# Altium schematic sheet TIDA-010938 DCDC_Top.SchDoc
size 431 x 279 mm; Date: Not shown in title block; ApprovedBy: Not shown in title block; CheckedBy: Not shown in title block; Author: Not shown in title block; CompanyName: Not shown in title block; Engineer: Not shown in title block; Organization: Not shown in title block; Address1: Not shown in title block; Address2: Not shown in title block; Address3: Not shown in title block; Address4: Not shown in title block; DocumentNumber: 1; Revision: Use project parameter SCH_Rev; SheetNumber: 2; SheetTotal: 9; PageSetup: Record=PageOptions¦CenterHorizontal=True¦CenterVertical=True¦PrintScale=1.00¦XCorrection=1.00¦YCorrection=1.00¦PrintKind=0¦BorderSize=5000000¦LeftOffset=0¦BottomOffset=0¦Orientation=2¦PaperLength=1000¦PaperWidth=1000¦Scale=100¦PaperSource=15¦PrintQuality=600¦MediaType=1¦DitherType=10¦PaperKind=Letter¦PrintScaleMode=1
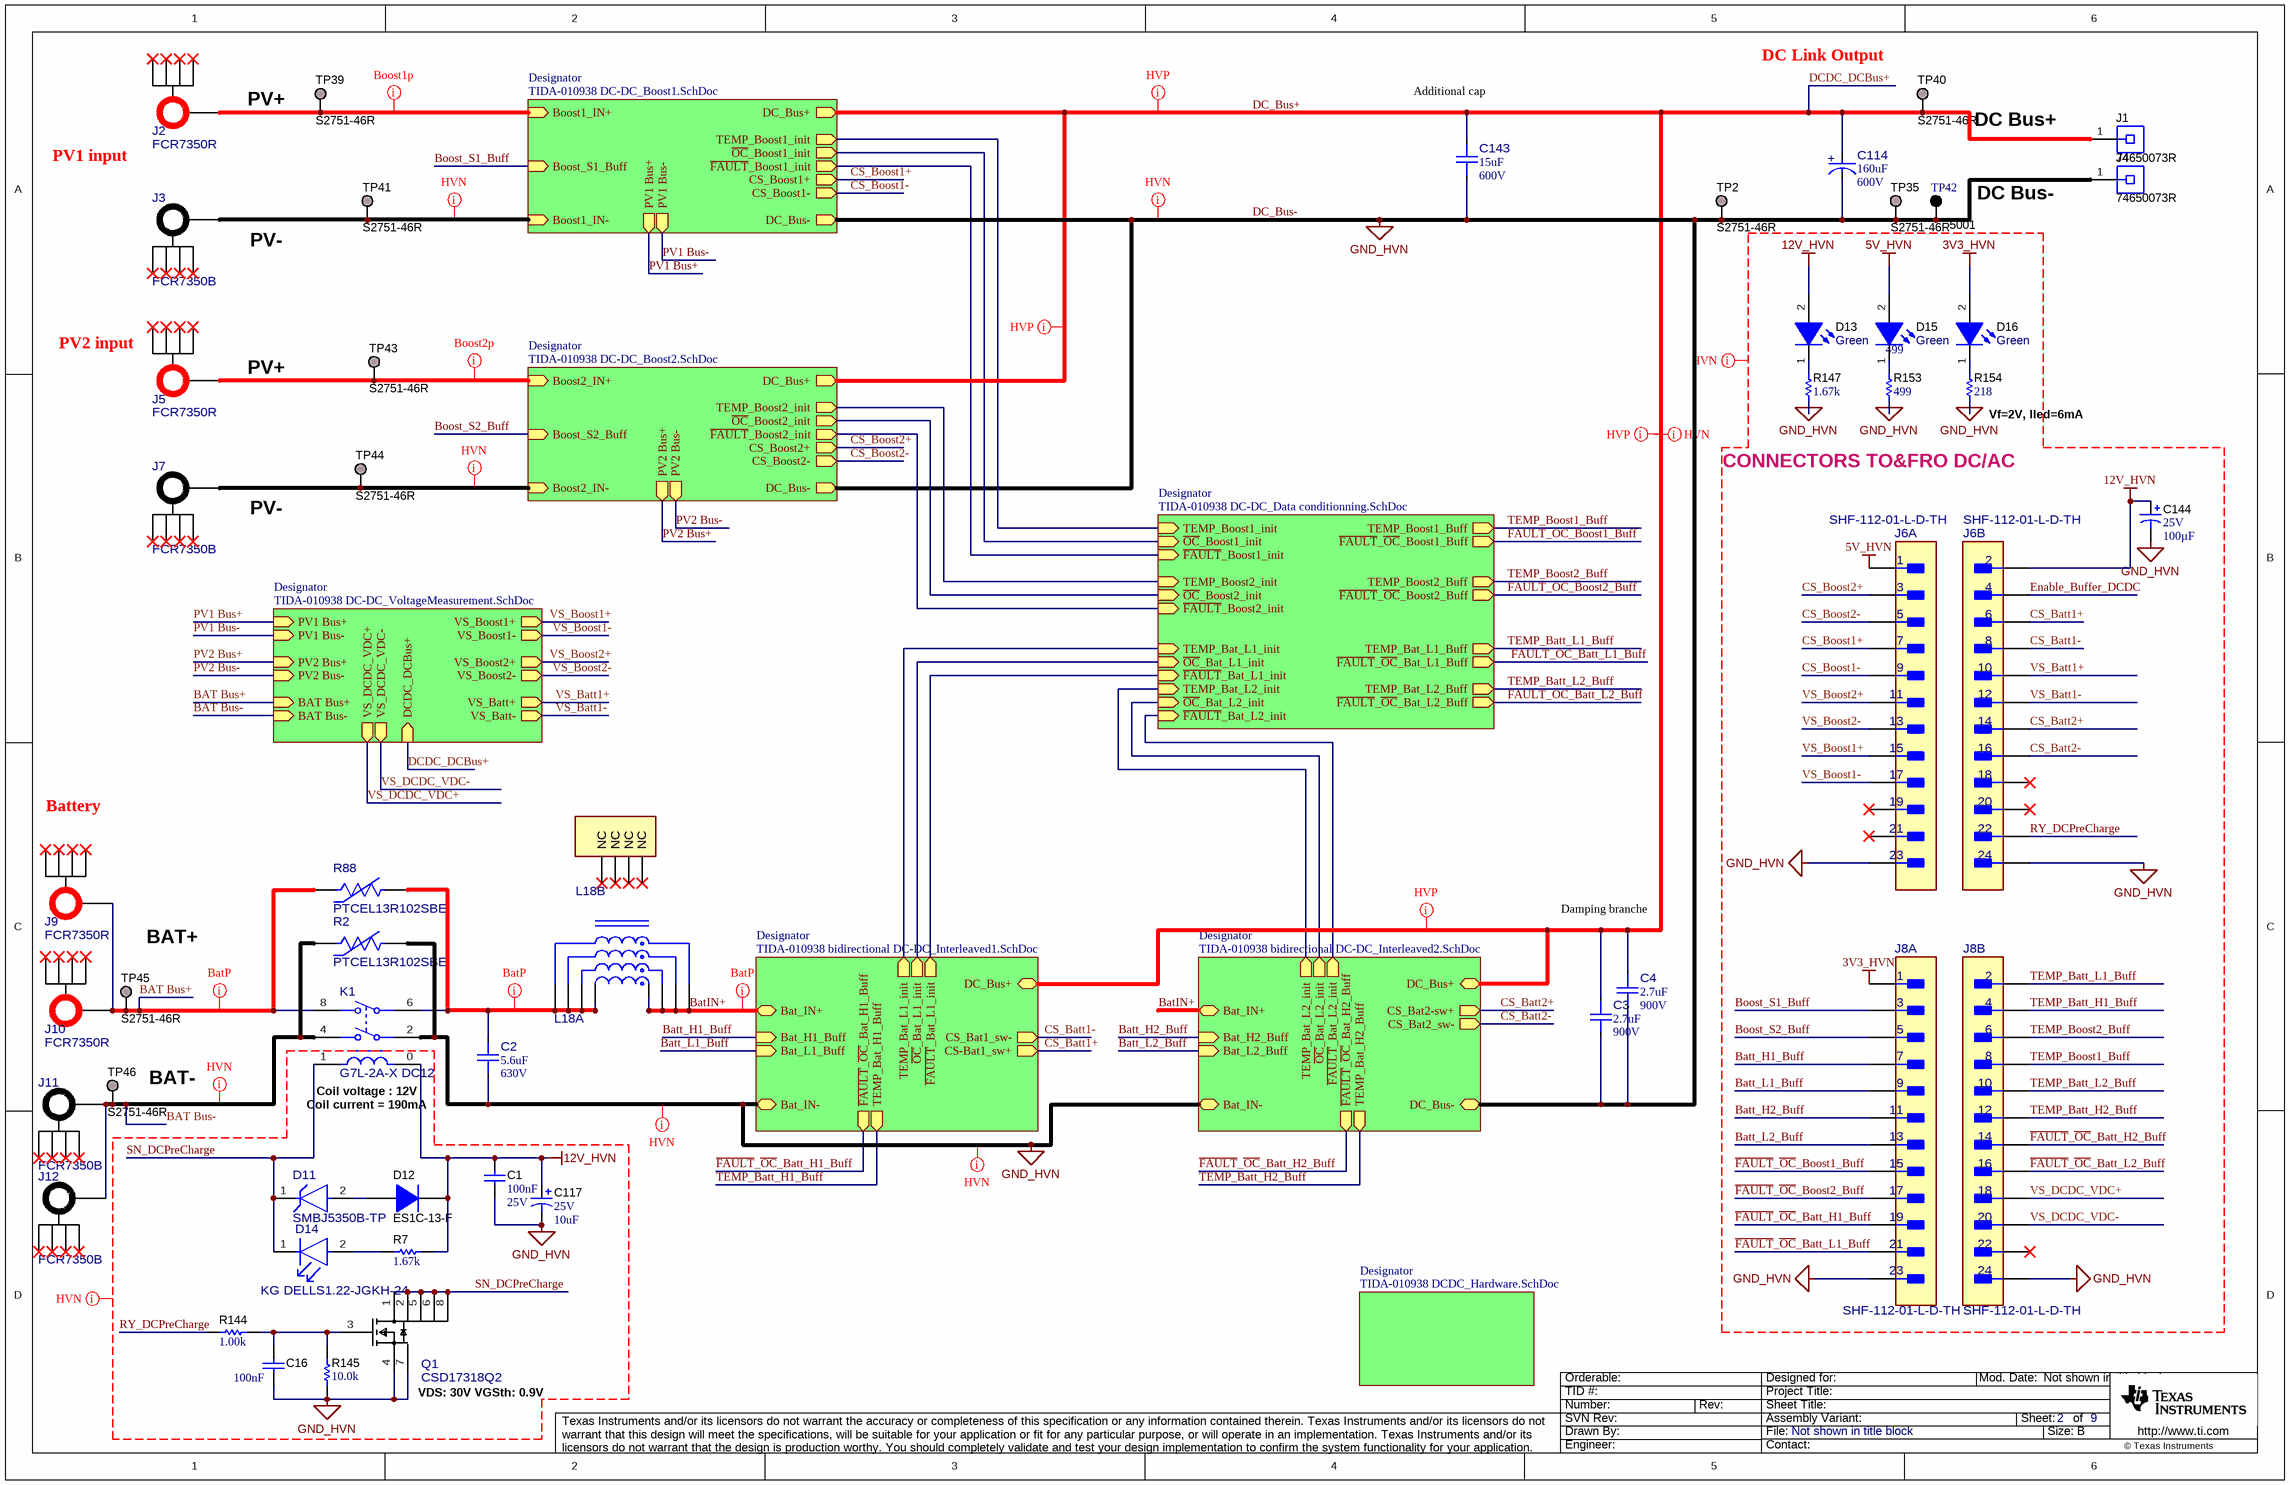
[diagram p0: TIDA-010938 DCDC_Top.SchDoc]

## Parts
C1  Cap_F: 100nF  VDC_V: 25V  [0603]  (hidden comment: 06033C104JAT2A)
C2  ValueDisplayed: 5.6uF  VDC_V: 630V  [FP-R533R456050P0M_RADIAL-MFG]  (hidden comment: R533R456050P0M)
C3  ValueDisplayed: 2.7uF  VDC_V: 900V  [FP-C4AKOBU4270A3YJ_RADIAL-MFG]  (hidden comment: C4AKOBU4270A3YJ)
C4  ValueDisplayed: 2.7uF  VDC_V: 900V  [FP-C4AKOBU4270A3YJ_RADIAL-MFG]  (hidden comment: C4AKOBU4270A3YJ)
C16  Cap_F: 100nF  [0603]  (hidden comment: GRM188R72A104KA35J)
C114  ValueDisplayed: 160uF  VDC_V: 600V  [FP-ALH82D161DD600_RADIAL-MFG]  (hidden comment: ALH82D161DD600)
C117  VDC_V: 25V  ValueDisplayed: 10uF  [SM_RADIAL_8MM]  (hidden comment: 25SVP10M)
C143  ValueDisplayed: 15uF  VDC_V: 600V  [FP-C4AQHBU5150P12J_RADIAL-MFG]  (hidden comment: C4AQHBU5150P12J)
C144  VDC_V: 25V  ValueDisplayed: 100µF  [UWT_630x770]  (hidden comment: UWT1E101MCL1GS)
D11  SMBJ5350B-TP  [FP-SMBJ5350B-TP_SMB-MFG]
D12  ES1C-13-F  [SMA]
D13  value Green  [WL-SMCW_GREEN]  (hidden comment: 150060VS75000)
D14  KG DELLS1.22-JGKH-24  [FP-KG DELLS1.22-JGKH-24_0603-MFG]
D15  value Green  [WL-SMCW_GREEN]  (hidden comment: 150060VS75000)
D16  value Green  [WL-SMCW_GREEN]  (hidden comment: 150060VS75000)
J1  74650073R  [Wurth_WP-THRBU]
J2  FCR7350R  [FP-FCR7350R_CONN_BANANA_JACK-MFG]
J3  FCR7350B  [FP-FCR7350B_CONN_BANANA_JACK-MFG]
J4  74650073R  [Wurth_WP-THRBU]
J5  FCR7350R  [FP-FCR7350R_CONN_BANANA_JACK-MFG]
J6  SHF-112-01-L-D-TH  [FP-SHF-112-01-L-D-TH_HDR24-MFG]  (parts A,B of 2)
J7  FCR7350B  [FP-FCR7350B_CONN_BANANA_JACK-MFG]
J8  SHF-112-01-L-D-TH  [FP-SHF-112-01-L-D-TH_HDR24-MFG]  (parts A,B of 2)
J9  FCR7350R  [FP-FCR7350R_CONN_BANANA_JACK-MFG]
J10  FCR7350R  [FP-FCR7350R_CONN_BANANA_JACK-MFG]
J11  FCR7350B  [FP-FCR7350B_CONN_BANANA_JACK-MFG]
J12  FCR7350B  [FP-FCR7350B_CONN_BANANA_JACK-MFG]
K1  G7L-2A-X DC12  [FP-G7L-2A-X DC12_PTH_RELAY_52MM5_35MM5-MFG]
L18  145454  [FP-145454_PTH12-MFG]  (value not drawn)  (parts A,B of 2)
Q1  CSD17318Q2  [FP-CSD17318Q2_WSON6-MFG]
R2  PTCEL13R102SBE  [FP-PTCEL13R102SBE_RADIAL-MFG]
R7  ValueDisplayed: 1.67k  [0603]  (hidden comment: RT0603DRE071K67L)
R88  PTCEL13R102SBE  [FP-PTCEL13R102SBE_RADIAL-MFG]
R144  ValueDisplayed: 1.00k  [0603]  (hidden comment: RNCF0603TKY1K00)
R145  ValueDisplayed: 10.0k  [0603]  (hidden comment: RG1608P-103-B-T5)
R147  ValueDisplayed: 1.67k  [0603]  (hidden comment: RT0603DRE071K67L)
R153  value 499  [0603]  (hidden comment: CRCW0603499RFKEAC)
R154  ValueDisplayed: 218  [0603]  (hidden comment: RT0603DRE07218RL)
TP2  S2751-46R  [Harwin_S2751-46R]  (no BOM)
TP35  S2751-46R  [Harwin_S2751-46R]  (no BOM)
TP39  S2751-46R  [Harwin_S2751-46R]  (no BOM)
TP40  S2751-46R  [Harwin_S2751-46R]  (no BOM)
TP41  S2751-46R  [Harwin_S2751-46R]  (no BOM)
TP42  5001  [Keystone5001]
TP43  S2751-46R  [Harwin_S2751-46R]  (no BOM)
TP44  S2751-46R  [Harwin_S2751-46R]  (no BOM)
TP45  S2751-46R  [Harwin_S2751-46R]  (no BOM)
TP46  S2751-46R  [Harwin_S2751-46R]  (no BOM)

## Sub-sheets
Designator = TIDA-010938 DC-DC_Boost1.SchDoc: Boost_S1_Buff (in), TEMP_Boost1_init (out), ~{FAULT}_Boost1_init (out), ~{OC}_Boost1_init (out), DC_Bus+ (out), DC_Bus- (out), Boost1_IN+ (in), Boost1_IN- (in), CS_Boost1+ (out), CS_Boost1- (out), PV1 Bus+ (out), PV1 Bus- (out)
Designator = TIDA-010938 DC-DC_Boost2.SchDoc: DC_Bus+ (out), DC_Bus- (out), Boost_S2_Buff (in), TEMP_Boost2_init (out), ~{FAULT}_Boost2_init (out), ~{OC}_Boost2_init (out), Boost2_IN+ (in), Boost2_IN- (in), CS_Boost2+ (out), CS_Boost2- (out), PV2 Bus+ (out), PV2 Bus- (out)
Designator = TIDA-010938 bidirectional DC-DC_Interleaved1.SchDoc: DC_Bus+ (bidir), Bat_IN+ (bidir), Bat_IN- (bidir), Bat_L1_Buff (in), Bat_H1_Buff (in), ~{FAULT}_Bat_L1_init (out), ~{FAULT}_~{OC}_Bat_H1_Buff (out), ~{OC}_Bat_L1_init (out), TEMP_Bat_H1_Buff (out), TEMP_Bat_L1_init (out), CS_Bat1_sw- (out), CS-Bat1_sw+ (out)
Designator = TIDA-010938 DC-DC_VoltageMeasurement.SchDoc: PV1 Bus+ (in), PV2 Bus+ (in), VS_Boost2+ (out), BAT Bus+ (in), BAT Bus- (in), VS_Batt+ (out), VS_Boost1+ (out), VS_Batt- (out), VS_Boost2- (out), VS_Boost1- (out), PV2 Bus- (in), PV1 Bus- (in), DCDC_DCBus+ (in), VS_DCDC_VDC+ (out), VS_DCDC_VDC- (out)
Designator = TIDA-010938 DC-DC_Data conditionning.SchDoc: ~{FAULT}_Boost1_init (in), ~{OC}_Boost1_init (in), ~{FAULT}_Boost2_init (in), ~{OC}_Boost2_init (in), ~{FAULT}_Bat_L1_init (in), ~{OC}_Bat_L1_init (in), ~{FAULT}_Bat_L2_init (in), ~{OC}_Bat_L2_init (in), TEMP_Boost1_init (in), TEMP_Boost2_init (in), TEMP_Bat_L1_init (in), TEMP_Bat_L2_init (in), TEMP_Boost1_Buff (out), ~{FAULT}_~{OC}_Boost1_Buff (out), TEMP_Boost2_Buff (out), ~{FAULT}_~{OC}_Boost2_Buff (out), TEMP_Bat_L1_Buff (out), ~{FAULT}_~{OC}_Bat_L1_Buff (out), TEMP_Bat_L2_Buff (out), ~{FAULT}_~{OC}_Bat_L2_Buff (out)
Designator = TIDA-010938 bidirectional DC-DC_Interleaved2.SchDoc: DC_Bus+ (bidir), DC_Bus- (bidir), Bat_IN+ (bidir), Bat_IN- (bidir), Bat_L2_Buff (in), Bat_H2_Buff (in), TEMP_Bat_H2_Buff (out), ~{FAULT}_~{OC}_Bat_H2_Buff (out), ~{FAULT}_Bat_L2_init (out), ~{OC}_Bat_L2_init (out), TEMP_Bat_L2_init (out), CS_Bat2-sw+ (out), CS_Bat2_sw- (out)
Designator = TIDA-010938 DCDC_Hardware.SchDoc: no entries

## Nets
3V3_HVN: D16.2(A) J8.1
5V_HVN: D15.2(A) J6.1
12V_HVN: C1.2 C117.1(+) C144.1(+) D12.1(K) D13.2(A) J6.2 K1.0 R7.1
DC_Bus-: C1.1 C2.1 C3.2 C4.2 C16.2 C114.1(CATHODE) C117.2(-) C143.1 C144.2(-) J4.1 J6.23 J6.24 J8.23 J8.24 K1.2 Q1.4(S) Q1.7(S) R2.2 R145.2 R147.1 R153.1 R154.1 TP2.1 TP35.1 TP42.1 ; sheet Designator/DC_Bus-, sheet Designator/DC_Bus-, sheet Designator/Bat_IN-, sheet Designator/DC_Bus-, sheet Designator/Bat_IN-  [also labelled GND_HVN]
BAT Bus+: J9.1 J10.1 K1.8 R88.1 TP45.1 ; sheet Designator/BAT Bus+
BAT Bus-: J11.1 J12.1 K1.4 R2.1 TP46.1 ; sheet Designator/BAT Bus-
BatIN+: L18.1 L18.2 L18.3 L18.4 ; sheet Designator/Bat_IN+, sheet Designator/Bat_IN+
Batt_H1_Buff: J8.7 ; sheet Designator/Bat_H1_Buff
Batt_H2_Buff: J8.11 ; sheet Designator/Bat_H2_Buff
Batt_L1_Buff: J8.9 ; sheet Designator/Bat_L1_Buff
Batt_L2_Buff: J8.13 ; sheet Designator/Bat_L2_Buff
Boost_S1_Buff: J8.3 ; sheet Designator/Boost_S1_Buff
Boost_S2_Buff: J8.5 ; sheet Designator/Boost_S2_Buff
CS_Batt1+: J6.6 ; sheet Designator/CS-Bat1_sw+
CS_Batt1-: J6.8 ; sheet Designator/CS_Bat1_sw-
CS_Batt2+: J6.14 ; sheet Designator/CS_Bat2-sw+
CS_Batt2-: J6.16 ; sheet Designator/CS_Bat2_sw-
CS_Boost1+: J6.7 ; sheet Designator/CS_Boost1+
CS_Boost1-: J6.9 ; sheet Designator/CS_Boost1-
CS_Boost2+: J6.3 ; sheet Designator/CS_Boost2+
CS_Boost2-: J6.5 ; sheet Designator/CS_Boost2-
DC_Bus+: C3.1 C4.1 C114.2(ANODE) C143.2 J1.1 TP40.1 ; sheet Designator/DC_Bus+, sheet Designator/DC_Bus+, sheet Designator/DC_Bus+, sheet Designator/DCDC_DCBus+, sheet Designator/DC_Bus+  [also labelled DCDC_DCBus+]
Enable_Buffer_DCDC: J6.4
~{FAULT}_~{OC}_Batt_H1_Buff: J8.19 ; sheet Designator/~{FAULT}_~{OC}_Bat_H1_Buff
~{FAULT}_~{OC}_Batt_H2_Buff: J8.14 ; sheet Designator/~{FAULT}_~{OC}_Bat_H2_Buff
~{FAULT}_~{OC}_Batt_L1_Buff: J8.21 ; sheet Designator/~{FAULT}_~{OC}_Bat_L1_Buff
~{FAULT}_~{OC}_Batt_L2_Buff: J8.16 ; sheet Designator/~{FAULT}_~{OC}_Bat_L2_Buff
~{FAULT}_~{OC}_Boost1_Buff: J8.15 ; sheet Designator/~{FAULT}_~{OC}_Boost1_Buff
~{FAULT}_~{OC}_Boost2_Buff: J8.17 ; sheet Designator/~{FAULT}_~{OC}_Boost2_Buff
PV1 Bus+: sheet Designator/PV1 Bus+, sheet Designator/PV1 Bus+
PV1 Bus-: sheet Designator/PV1 Bus-, sheet Designator/PV1 Bus-
PV2 Bus+: sheet Designator/PV2 Bus+, sheet Designator/PV2 Bus+
PV2 Bus-: sheet Designator/PV2 Bus-, sheet Designator/PV2 Bus-
RY_DCPreCharge: J6.22 R144.1
SN_DCPreCharge: D11.1(CATHODE) D14.1(CATHODE) K1.1 Q1.1(D) Q1.2(D) Q1.5(D) Q1.6(D) Q1.8(D)
TEMP_Batt_H1_Buff: J8.4 ; sheet Designator/TEMP_Bat_H1_Buff
TEMP_Batt_H2_Buff: J8.12 ; sheet Designator/TEMP_Bat_H2_Buff
TEMP_Batt_L1_Buff: J8.2 ; sheet Designator/TEMP_Bat_L1_Buff
TEMP_Batt_L2_Buff: J8.10 ; sheet Designator/TEMP_Bat_L2_Buff
TEMP_Boost1_Buff: J8.8 ; sheet Designator/TEMP_Boost1_Buff
TEMP_Boost2_Buff: J8.6 ; sheet Designator/TEMP_Boost2_Buff
VS_Batt1+: J6.10 ; sheet Designator/VS_Batt+
VS_Batt1-: J6.12 ; sheet Designator/VS_Batt-
VS_Boost1+: J6.15 ; sheet Designator/VS_Boost1+
VS_Boost1-: J6.17 ; sheet Designator/VS_Boost1-
VS_Boost2+: J6.11 ; sheet Designator/VS_Boost2+
VS_Boost2-: J6.13 ; sheet Designator/VS_Boost2-
VS_DCDC_VDC+: J8.18 ; sheet Designator/VS_DCDC_VDC+
VS_DCDC_VDC-: J8.20 ; sheet Designator/VS_DCDC_VDC-
NetC2_2: C2.2 K1.6 L18.9 L18.10 L18.11 L18.12 R88.2
NetC16_1: C16.1 Q1.3(G) R144.2 R145.1
NetD11_2: D11.2(ANODE) D12.2(A)
NetD13_1: D13.1(K) R147.2
NetD14_2: D14.2(ANODE) R7.2
NetD15_1: D15.1(K) R153.2
NetD16_1: D16.1(K) R154.2
NetJ2_1: J2.1 TP39.1 ; sheet Designator/Boost1_IN+
NetJ3_1: J3.1 TP41.1 ; sheet Designator/Boost1_IN-
NetJ5_1: J5.1 TP43.1 ; sheet Designator/Boost2_IN+
NetJ7_1: J7.1 TP44.1 ; sheet Designator/Boost2_IN-
(unnamed): sheet Designator/TEMP_Boost1_init, sheet Designator/TEMP_Boost1_init
(unnamed): sheet Designator/~{FAULT}_Boost1_init, sheet Designator/~{FAULT}_Boost1_init  [a separate net that carries the same name]
(unnamed): sheet Designator/~{OC}_Boost1_init, sheet Designator/~{OC}_Boost1_init  [a separate net that carries the same name]
(unnamed): sheet Designator/TEMP_Boost2_init, sheet Designator/TEMP_Boost2_init  [a separate net that carries the same name]
(unnamed): sheet Designator/~{FAULT}_Boost2_init, sheet Designator/~{FAULT}_Boost2_init  [a separate net that carries the same name]
(unnamed): sheet Designator/~{OC}_Boost2_init, sheet Designator/~{OC}_Boost2_init  [a separate net that carries the same name]
(unnamed): sheet Designator/~{FAULT}_Bat_L1_init, sheet Designator/~{FAULT}_Bat_L1_init  [a separate net that carries the same name]
(unnamed): sheet Designator/~{OC}_Bat_L1_init, sheet Designator/~{OC}_Bat_L1_init  [a separate net that carries the same name]
(unnamed): sheet Designator/TEMP_Bat_L1_init, sheet Designator/TEMP_Bat_L1_init  [a separate net that carries the same name]
(unnamed): sheet Designator/~{FAULT}_Bat_L2_init, sheet Designator/~{FAULT}_Bat_L2_init  [a separate net that carries the same name]
(unnamed): sheet Designator/~{OC}_Bat_L2_init, sheet Designator/~{OC}_Bat_L2_init  [a separate net that carries the same name]
(unnamed): sheet Designator/TEMP_Bat_L2_init, sheet Designator/TEMP_Bat_L2_init  [a separate net that carries the same name]

Not connected (* = marked no-connect by the designer): J2 2(MNT_1)* 3(MNT_2)* 4(MNT_3)* 5(MNT_4)*; J3 2(MNT_1)* 3(MNT_2)* 4(MNT_3)* 5(MNT_4)*; J5 2(MNT_1)* 3(MNT_2)* 4(MNT_3)* 5(MNT_4)*; J6 18* 19* 20* 21*; J7 2(MNT_1)* 3(MNT_2)* 4(MNT_3)* 5(MNT_4)*; J8 22*; J9 2(MNT_1)* 3(MNT_2)* 4(MNT_3)* 5(MNT_4)*; J10 2(MNT_1)* 3(MNT_2)* 4(MNT_3)* 5(MNT_4)*; J11 2(MNT_1)* 3(MNT_2)* 4(MNT_3)* 5(MNT_4)*; J12 2(MNT_1)* 3(MNT_2)* 4(MNT_3)* 5(MNT_4)*; L18 5(NC)* 6(NC)* 7(NC)* 8(NC)*

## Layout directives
net class HVN: 3V3_HVN, 5V_HVN, 12V_HVN, (no net found under the mark), BAT Bus-, Batt_H1_Buff, Batt_H2_Buff, Batt_L1_Buff, Batt_L2_Buff, Boost_S1_Buff, Boost_S2_Buff, CS_Batt1+, CS_Batt1-, CS_Batt2+, CS_Batt2-, CS_Boost1+, CS_Boost1-, CS_Boost2+, CS_Boost2-, DC_Bus-, Enable_Buffer_DCDC, GND_HVN, NetJ3_1, NetJ7_1, RY_DCPreCharge, SN_DCPreCharge, TEMP_Batt_H1_Buff, TEMP_Batt_H2_Buff, TEMP_Batt_L1_Buff, TEMP_Batt_L2_Buff, TEMP_Boost1_Buff, TEMP_Boost2_Buff, VS_Batt1+, VS_Batt1-, VS_Boost1+, VS_Boost1-, VS_Boost2+, VS_Boost2-, VS_DCDC_VDC+, VS_DCDC_VDC-, ~{FAULT}_~{OC}_Batt_H1_Buff, ~{FAULT}_~{OC}_Batt_H2_Buff, ~{FAULT}_~{OC}_Batt_L1_Buff, ~{FAULT}_~{OC}_Batt_L2_Buff, ~{FAULT}_~{OC}_Boost1_Buff, ~{FAULT}_~{OC}_Boost2_Buff
net class Boost1p: NetJ2_1
net class Boost2p: NetJ5_1
net class HVP: DC_Bus+
net class BatP: BAT Bus+, BatIN+, NetC2_2

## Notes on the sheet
- PV+
- (near C143) Additional cap
- DC Link Output
- PV1 input
- DC Bus+
- DC Bus-
- PV-
- (near J5) PV2 input
- (near R154) Vf=2V, Iled=6mA
- CONNECTORS TO&FRO DC/AC
- Battery
- BAT+
- Damping branche
- (near TP46) BAT-
- (near K1) Coil voltage : 12V
- (near K1) Coil current = 190mA
- (near Q1) VDS: 30V VGSth: 0.9V

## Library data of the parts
C1 = CMP-0006752-5: CAP, CERM, 0.1 uF, 25 V, +/- 5%, X7R, 0603; Manufacturer: AVX; TaMin_C: -55°C; ESR_ohm: 0.05; Polarized: N; SizeAreaWB_mm2: 4.68; Value1: 0.05 ohm; U/M: EA; Value: 0.1uF; TaMax_C: 125°C; SizeZ_mm: 1; SizeX_mm: 1.6; SizeY_mm: 0.8; SizeArea_mm2: 1.28; AEC Category: Q200
C2 = CMP-0045188-1: 5.6 µF Film Capacitor 310V 630V Polypropylene (PP), Metallized Radial; Manufacturer: KEMET; AEC Grade: Grade 3; AEC Qualified: Yes; Cap_F: 5.6µF; SizeZ_mm: 30.3mm; Tolerance_%: 20%; VAC_X: X2; Value: 5.6µF
C3 C4 = CMP-0045062-1: 2.7 µF Film Capacitor 900V Polypropylene (PP), Metallized Radial; Manufacturer: Kemet; AEC Grade: Grade 1; AEC Qualified: Yes; Cap_F: 2.7µF; SizeZ_mm: 28.7mm; Tolerance_%: 5%; Value: 2.7µF
C16 = CMP-0007470-5: CAP, CERM, 0.1 uF, 100 V, +/- 10%, X7R, 0603; Manufacturer: MuRata; TaMin_C: -55°C; Polarized: N; SizeAreaWB_mm2: 4.68; Value1: Unknown; U/M: EA; Value: 0.1uF; TaMax_C: 125°C; SizeZ_mm: 1; SizeX_mm: 1.6; SizeY_mm: 0.8; Value2: 100V; SizeArea_mm2: 1.28; AEC Category: Q200
C114 = CMP-0033686-1: ALH82, Aluminum Electrolytic, 160 uF, 20%, 600 VDC, -40/+105°C; Manufacturer: KEMET; AEC Qualified: No; Cap_F: 160µF; IRMS_A: 4.51A; SizeZ_mm: 42mm; Esr: 0.877; Leakage Current: 288uA; Life: 3000Hours; Value: 160µF
C117 = CMP-0012113-3: CAP, Aluminum Polymer, 10 uF, 25 V, +/- 20%, 0.06 ohm, 8x10 SMD; Manufacturer: Panasonic; TaMin_C: -55°C; ESR_ohm: 0.06; Polarized: Y; SizeAreaWB_mm2: 113.3; Value: 10uF; TaMax_C: 105°C; SizeZ_mm: 10.2; SizeX_mm: 9; SizeY_mm: 8.3; Cap_Case: 8.3x8.3x6.9; SizeArea_mm2: 74.7; CompType: Capacitor; Cap_F: 10µF; IRMS_A: 1.5A; AEC Category: Q200
C143 = CMP-0123402-1: 15 µF Film Capacitor 600V Polypropylene (PP), Metallized Radial; Manufacturer: KEMET; AEC Grade: Grade 1; AEC Qualified: Yes; Cap_F: 15µF; SizeZ_mm: 37.2mm; Tolerance_%: 5%; Value: 15µF
C144 = CMP-0081462-1: CAP, AL, 100 µF, 25 V, +/- 20%, SMD; Manufacturer: Nichicon; TaMin_C: -55°C; Polarized: Y; SizeAreaWB_mm2: 77.4; U/M: EA; Value: 100uF; TaMax_C: 105°C; SizeZ_mm: 8; SizeX_mm: 7; SizeY_mm: 6.6; Cap_Case: 6.3x7.7mm; SizeArea_mm2: 46.2; CompType: Capacitor; AEC Qualified: N; IRMS_A: 91mA; AEC Category: Q200
D11 = CMP-0097215-1: Zener Diode 13 V 5 W ±5% Surface Mount DO-214AA (SMB); Manufacturer: MCC; Power_W: 5W; Standoff Height: 0.05mm; Vr_V: 9.9V; SizeZ_mm: 2.62mm; Zener Impedance: 2.5Ω; AEC Qualified: No; Max Reverse Leakage Current: 1uA; Vz_V: 13V; Vf_V: 13.65V; TJmax_C: 150°C
D12 = CMP-0029023-2: Diode, Superfast Rectifier, 150 V, 1 A, SMA; Manufacturer: Diodes Inc.; TJmax_C: 150°C; Vr_V: 150V; Value2: 0.92V; SizeX_mm: 5.59; Green_REACh: Incomplete; SizeAreaWB_mm2: 37.3428; Value: 150V; Vf_V: 920mV; Green_Lifecycle: Not Set; Value1: 1A; SizeZ_mm: 2.87; SizeArea_mm2: 16.3228; SizeY_mm: 2.92; AEC Category: Q101; RJC_CperW: 25
D13 D15 D16 = CMP-0002894-2: LED, Green, SMD; Manufacturer: Wurth Elektronik; Type: AlInGaP; Value2: 2V; Io_A: 20mA; Value1: W
D14 = CMP-0093310-1: Standard LEDs - SMD Green TOPLED E 1608; Manufacturer: Osram Opto; AEC Grade: Grade 2; LambdaP: 572nm; SizeZ_mm: 0.7mm; LuminousFlux_PhiV: 0.016-0.0295lm; Luminous Intensity: 4.5-9.7mcd; LambdaD: 570nm; Tjmax_C: 125°C; Angle: 120°; Led Orientation: Top View; Forward Current: 2mA; Vf_V: 1.8V; AEC Qualified: Yes; Vr_V: 12V
J1 J4 = CMP-0078526-1: Power Element Bush, M3, TH; Manufacturer: Wurth Elektronik; Gender: Female; Current_A: 50A; ContactFinish: Tin; CompType: Screw Terminal
J2 J5 J9 J10 = CMP-0032022-2: Banana Jack Connector Standard Banana Solder Red; Manufacturer: CLIFF Electronic Components; ContactFinish: Gold; Current_A: 24A; Voltage_V: 1kV; AEC Qualified: No; Conn Orientation: Horizontal; Is Female: yes; SizeZ_mm: 12.5mm; Standoff Height: 0.7mm
J3 J7 J11 J12 = CMP-0032021-2: Banana Jack Connector Standard Banana Solder Black; Manufacturer: CLIFF Electronic Components; ContactFinish: Gold; Current_A: 24A; Voltage_V: 1kV; AEC Qualified: No; Conn Orientation: Horizontal; Is Female: yes; SizeZ_mm: 12.5mm; Standoff Height: 0.7mm
J6 J8 = CMP-0003796-1: Conn Shrouded Header (4 Sides) HDR 24 POS 1.27mm Solder ST Top Entry Thru-Hole Tube; Manufacturer: Samtec; ContactFinish: Gold,Nickel; Row_Count: 2; AEC Qualified: No; Conn Gender: Male; Conn Orientation: Straight; SizeZ_mm: 5.46mm; Standoff Height: 0.38mm
K1 = CMP-0093885-1: General Purpose Relay DPST-NO (2 Form A) 12VDC Coil Through Hole; Manufacturer: Omron; SizeZ_mm: 41mm; Coil Power_W: 2.3W; TaMax_C: +85°C; Switching Current: 30A; TaMin_C: -40°C; Coil Voltage_VDC: 12V; Coil Current_A: 191.7mA; Coil Resistance: 63Ω; Coil Type: Non-Latching; AEC Qualified: No
L18 = CMP-0123020-1: Inductor 22 μH 10% 5mΩ; Manufacturer: Bourns; AEC Qualified: No; DCR_ohm: 5.5m; Ind_H: 22µH; Isat: 35A; SizeZ_mm: 40.9mm; Value: 22uH; Test Frequency: 100kHz
Q1 = CMP-0076725-1: 30-V N-Channel NexFET™ Power MOSFET; Manufacturer: Texas Instruments; VdsMax_V: 30V; SizeZ_mm: 0.8mm; ChMode: False; QgTyp_nC: 6nC @ 4.5V; Rdson45_ohm: 0.0139; Vgs_V: 10V; AEC Qualified: No; IdsMax_A: 10A
R2 R88 = CMP-0043438-1: PTCEL Series 850 V 1 kOhm ±30 % Radial Inrush Current Limiter PTC Thermistor; Manufacturer: Vishay; SizeZ_mm: 17mm; Value: 1000Ω; AEC Grade: Grade 2; AEC Qualified: Yes; Hold Current: 30mA; Max Current: 40A; Standoff Height: 2mm; Tolerance_%: 30%; VDC_V: 850V
R7 R147 = CMP-0024836-3: RES, 1.67 k, 0.5%, 0.1 W, 0603; Manufacturer: Yageo America; Power_W: 100mW; TempCo: 50 ppm/C; Value_Code: 1k67; U/M: EA; Value: 1.67k; EIA_Code: E192; SizeX_mm: 1.6; SizeY_mm: 0.8; SizeZ_mm: 1; Value2: 0.1W; SizeArea_mm2: 1.28; VDC_V: 75V; AEC Category: Q200
R144 = CMP-0023627-2: RES, 1.00 k, 0.01%, 0.063 W, 0603; Manufacturer: Stackpole Electronics Inc; Power_W: 63mW; TempCo: 5 ppm/C; Value_Code: 1k00; U/M: EA; Value: 1.00k; Res_ohm: 1k; SizeX_mm: 1.6; SizeY_mm: 0.8; SizeZ_mm: 1; Value2: 0.063W; SizeArea_mm2: 1.28; VDC_V: 50V; AEC Category: Q200
R145 = CMP-0023404-1: RES, 10.0 k, 0.1%, 0.1 W, 0603; Manufacturer: Susumu Co Ltd; Power_W: 100mW; TempCo: 25 ppm/C; Value_Code: 10k0; U/M: EA; Value: 10.0k; EIA_Code: E192; Res_ohm: 10k; SizeX_mm: 1.6; SizeY_mm: 0.8; SizeZ_mm: 1; Value2: 0.1W; SizeArea_mm2: 1.28; VDC_V: 75V; AEC Category: Q200
R153 = CMP-0082532-1: RES, 499, 1%, 0.1 W, 0603; Manufacturer: Vishay-Dale; Power_W: 100mW; TempCo: 100 ppm/C; SizeAreaWB_mm2: 4.68; Value_Code: 499R; EIA_Code: E96; SizeX_mm: 1.6; SizeY_mm: 0.8; SizeZ_mm: 1; Value2: 0.1W; SizeArea_mm2: 1.28; AEC Qualified: N; VDC_V: 75V; AEC Category: Q200
R154 = CMP-0024934-2: RES, 218, 0.5%, 0.1 W, 0603; Manufacturer: Yageo America; Power_W: 100mW; TempCo: 50 ppm/C; Value_Code: 218R; U/M: EA; Value: 218; EIA_Code: E192; SizeX_mm: 1.6; SizeY_mm: 0.8; SizeZ_mm: 1; Value2: 0.1W; SizeArea_mm2: 1.28; VDC_V: 75V; AEC Category: Q200
TP2 TP35 TP39-TP41 TP43-TP46 = CMP-0003968-1: Test Point, SMT; Manufacturer: Harwin
TP42 = CMP-0055138-2: Test Point, Miniature, Black, TH; Manufacturer: Keystone Electronics; ContactFinish: Silver; CNHeader: FALSE; Green_Lifecycle: Active; Green_REACh: Passed; CT: TRUE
